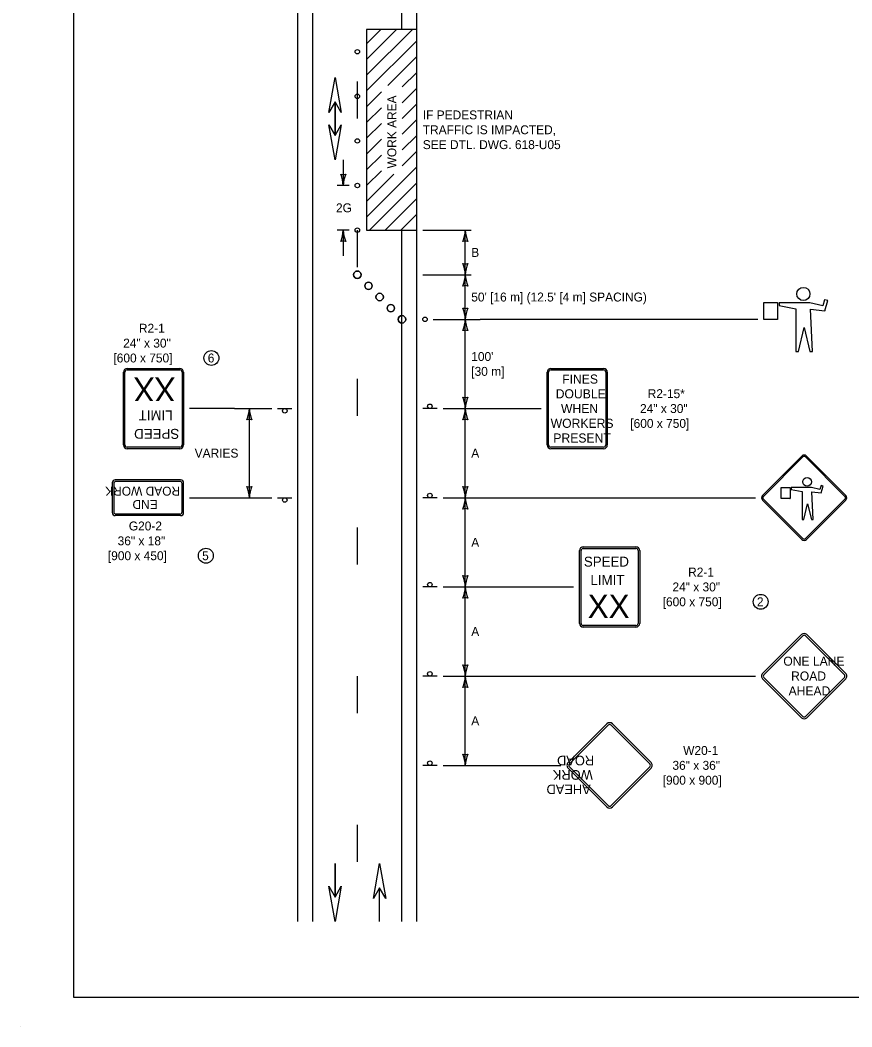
# Model space of a CAD drawing. Extents: x 49991.4 to 50021, y 49987.6 to 50011.4.
# Drawn here: x 49999.98 to 50005.57, y 49999.86 to 50006.63 of the extents above; entities that cross this region are included whole.
import ezdxf

# ---------------------------------------------------------------- set-up
doc = ezdxf.new("R2010")
doc.units = 0
for name, color, linetype in [('Level 1', 7, 'Continuous'), ('Level 2', 7, 'Continuous'), ('Level 3', 7, 'Continuous')]:
    doc.layers.add(name, color=color, linetype=linetype)

msp = doc.modelspace()

# ---------------------------------------------------------------- linework, layer by layer
at = {"layer": 'Level 1'}
for p, q in [((50001.8443, 50000.5714), (50001.8443, 50010.7538)), ((50001.9443, 50000.5714), (50001.9443, 50010.7538)), ((50002.5443, 50006.5714), (50002.5443, 50010.7538)), ((50002.6443, 50000.5714), (50002.6443, 50010.7538)), ((50002.3068, 50006.5714), (50002.3068, 50005.2214)), ((50002.3068, 50006.2634), (50002.6148, 50006.5714)), ((50002.3068, 50006.3694), (50002.5087, 50006.5714)), ((50002.3068, 50006.4755), (50002.4027, 50006.5714)), ((50002.6443, 50006.5714), (50002.3068, 50006.5714)), ((50002.3068, 50006.1573), (50002.6443, 50006.4948)), ((50002.4504, 50006.1948), (50002.6443, 50006.3887)), ((50002.5464, 50006.1847), (50002.6443, 50006.2827)), ((50002.2443, 50005.9716), (50002.2443, 50006.2216)), ((50002.3068, 50006.0512), (50002.4064, 50006.1508)), ((50002.5464, 50006.0787), (50002.6443, 50006.1766)), ((50002.094, 50006.0842), (50002.094, 50005.8583)), ((50002.0943, 50005.8584), (50002.0943, 50006.0843)), ((50002.0943, 50006.0842), (50002.0943, 50005.8583)), ((50002.0946, 50005.8584), (50002.0946, 50006.0843)), ((50002.5464, 50005.9726), (50002.6443, 50006.0705)), ((50002.3068, 50005.9452), (50002.4064, 50006.0447)), ((50002.3068, 50005.8391), (50002.4064, 50005.9387)), ((50002.5464, 50005.8665), (50002.6443, 50005.9645)), ((50002.5464, 50005.7605), (50002.6443, 50005.8584)), ((50002.3068, 50005.733), (50002.4064, 50005.8326)), ((50002.3068, 50005.627), (50002.4064, 50005.7265)), ((50002.5464, 50005.6544), (50002.6443, 50005.7523)), ((50002.3068, 50005.3088), (50002.6443, 50005.6463)), ((50002.3068, 50005.5209), (50002.4064, 50005.6205)), ((50002.3068, 50005.4148), (50002.4899, 50005.5979)), ((50002.3255, 50005.2214), (50002.6443, 50005.5402)), ((50002.4315, 50005.2214), (50002.6443, 50005.4341)), ((50002.5376, 50005.2214), (50002.6443, 50005.3281)), ((50002.2443, 50004.9716), (50002.2443, 50005.2216)), ((50002.3068, 50005.2214), (50002.6443, 50005.2214)), ((50002.5443, 50000.5714), (50002.5443, 50005.2214)), ((50002.6437, 50005.2214), (50002.6443, 50005.222)), ((50004.9783, 50004.6214), (50004.9783, 50004.7339)), ((50004.9783, 50004.7339), (50005.0702, 50004.7339)), ((50005.0702, 50004.7339), (50005.0702, 50004.6214)), ((50005.2874, 50004.7332), (50005.0805, 50004.7332)), ((50005.0805, 50004.7332), (50005.0805, 50004.7146)), ((50005.0805, 50004.7146), (50005.193, 50004.6924)), ((50005.3742, 50004.7132), (50005.2874, 50004.7332)), ((50005.3869, 50004.7528), (50005.3742, 50004.7132)), ((50005.4089, 50004.7473), (50005.3869, 50004.7528)), ((50005.3889, 50004.6785), (50005.4089, 50004.7473)), ((50001.9443, 50004.6448), (50001.9443, 50004.6811)), ((50005.193, 50004.6924), (50005.193, 50004.4061)), ((50005.3061, 50004.4061), (50005.2913, 50004.6895)), ((50005.2913, 50004.6895), (50005.3889, 50004.6785)), ((50005.0702, 50004.6214), (50004.9783, 50004.6214)), ((50005.2112, 50004.4061), (50005.2495, 50004.5674)), ((50005.2495, 50004.5674), (50005.2878, 50004.4061)), ((50005.193, 50004.4061), (50005.2112, 50004.4061)), ((50005.2878, 50004.4061), (50005.3061, 50004.4061)), ((50000.6709, 50003.7766), (50000.6709, 50004.2661)), ((50000.6815, 50003.7766), (50000.6815, 50004.2661)), ((50000.6963, 50004.2914), (50001.0507, 50004.2914)), ((50000.6963, 50004.2809), (50001.0507, 50004.2809)), ((50001.0655, 50004.2661), (50001.0655, 50003.7766)), ((50001.076, 50004.2661), (50001.076, 50003.7766)), ((50003.5203, 50003.7766), (50003.5203, 50004.2661)), ((50003.5308, 50003.7766), (50003.5308, 50004.2661)), ((50003.5456, 50004.2914), (50003.9, 50004.2914)), ((50003.5456, 50004.2809), (50003.9, 50004.2809)), ((50003.7228, 50004.2914), (50003.7228, 50004.2914)), ((50003.9148, 50004.2661), (50003.9148, 50003.7766)), ((50003.9254, 50004.2661), (50003.9254, 50003.7766)), ((50002.2443, 50003.9716), (50002.2443, 50004.2216)), ((50001.7083, 50004.0214), (50001.8043, 50004.0214)), ((50002.7803, 50004.0214), (50002.6843, 50004.0214)), ((50001.0507, 50003.7619), (50000.6963, 50003.7619)), ((50003.9, 50003.7619), (50003.5456, 50003.7619)), ((50001.0507, 50003.7513), (50000.6963, 50003.7513)), ((50000.8735, 50003.7513), (50000.8735, 50003.7513)), ((50003.9, 50003.7513), (50003.5456, 50003.7513)), ((50005.2336, 50003.702), (50004.9683, 50003.4368)), ((50005.2397, 50003.6959), (50004.9745, 50003.4306)), ((50005.5235, 50003.4306), (50005.2583, 50003.6959)), ((50005.5297, 50003.4368), (50005.2644, 50003.702)), ((50000.596, 50003.5214), (50000.596, 50003.3214)), ((50000.596, 50003.5214), (50000.596, 50003.3214)), ((50000.606, 50003.5164), (50000.606, 50003.3264)), ((50000.606, 50003.5164), (50000.606, 50003.3264)), ((50001.056, 50003.5414), (50000.616, 50003.5414)), ((50001.056, 50003.5414), (50000.616, 50003.5414)), ((50001.051, 50003.5314), (50000.621, 50003.5314)), ((50001.051, 50003.5314), (50000.621, 50003.5314)), ((50001.066, 50003.3264), (50001.066, 50003.5164)), ((50001.066, 50003.3264), (50001.066, 50003.5164)), ((50001.076, 50003.3214), (50001.076, 50003.5214)), ((50001.076, 50003.3214), (50001.076, 50003.5214)), ((50005.0934, 50003.4161), (50005.0934, 50003.4903)), ((50005.0934, 50003.4903), (50005.154, 50003.4903)), ((50005.154, 50003.4903), (50005.154, 50003.4161)), ((50005.2973, 50003.4899), (50005.1608, 50003.4899)), ((50005.1608, 50003.4899), (50005.1608, 50003.4776)), ((50005.3546, 50003.4767), (50005.2973, 50003.4899)), ((50005.3629, 50003.5029), (50005.3546, 50003.4767)), ((50005.3774, 50003.4992), (50005.3629, 50003.5029)), ((50005.3642, 50003.4538), (50005.3774, 50003.4992)), ((50001.7083, 50003.4214), (50001.8043, 50003.4214)), ((50002.7803, 50003.4214), (50002.6843, 50003.4214)), ((50005.1608, 50003.4776), (50005.235, 50003.463)), ((50005.235, 50003.463), (50005.235, 50003.2741)), ((50005.3095, 50003.2741), (50005.2998, 50003.4611)), ((50005.2998, 50003.4611), (50005.3642, 50003.4538)), ((50004.9683, 50003.4059), (50005.2336, 50003.1407)), ((50004.9745, 50003.4121), (50005.2397, 50003.1468)), ((50005.154, 50003.4161), (50005.0934, 50003.4161)), ((50005.247, 50003.2741), (50005.2722, 50003.3805)), ((50005.2583, 50003.1468), (50005.5235, 50003.4121)), ((50005.2644, 50003.1407), (50005.5297, 50003.4059)), ((50005.2722, 50003.3805), (50005.2975, 50003.2741)), ((50001.056, 50003.3014), (50000.616, 50003.3014)), ((50001.056, 50003.3014), (50000.616, 50003.3014)), ((50001.051, 50003.3114), (50000.621, 50003.3114)), ((50002.2443, 50002.9716), (50002.2443, 50003.2216)), ((50005.235, 50003.2741), (50005.247, 50003.2741)), ((50005.2975, 50003.2741), (50005.3095, 50003.2741)), ((50003.7635, 50003.0914), (50004.1179, 50003.0914)), ((50003.7635, 50003.0809), (50004.1179, 50003.0809)), ((50003.9407, 50003.0914), (50003.9407, 50003.0914)), ((50003.7382, 50002.5766), (50003.7382, 50003.0661)), ((50003.7487, 50002.5766), (50003.7487, 50003.0661)), ((50004.1327, 50003.0661), (50004.1327, 50002.5766)), ((50004.1432, 50003.0661), (50004.1432, 50002.5766)), ((50002.7803, 50002.8214), (50002.6843, 50002.8214)), ((50004.1179, 50002.5619), (50003.7635, 50002.5619)), ((50004.1179, 50002.5513), (50003.7635, 50002.5513)), ((50005.2303, 50002.5007), (50004.9696, 50002.24)), ((50005.2391, 50002.4919), (50004.9784, 50002.2312)), ((50005.2303, 50002.5007), (50005.2303, 50002.5007)), ((50005.2391, 50002.4919), (50005.2391, 50002.4919)), ((50005.5195, 50002.2312), (50005.2588, 50002.4919)), ((50005.5283, 50002.24), (50005.2676, 50002.5007)), ((50002.2443, 50001.9716), (50002.2443, 50002.2216)), ((50002.7803, 50002.2214), (50002.6843, 50002.2214)), ((50004.9696, 50002.2027), (50005.2303, 50001.942)), ((50004.9784, 50002.2115), (50005.2391, 50001.9508)), ((50005.2588, 50001.9508), (50005.5195, 50002.2115)), ((50005.2676, 50001.942), (50005.5283, 50002.2027)), ((50003.9221, 50001.9007), (50003.6613, 50001.64)), ((50003.9309, 50001.8919), (50003.6701, 50001.6312)), ((50003.9221, 50001.9007), (50003.9221, 50001.9007)), ((50003.9309, 50001.8919), (50003.9309, 50001.8919)), ((50004.2113, 50001.6312), (50003.9505, 50001.8919)), ((50004.22, 50001.64), (50003.9593, 50001.9007)), ((50002.7803, 50001.6214), (50002.6843, 50001.6214)), ((50003.6613, 50001.6027), (50003.9221, 50001.342)), ((50003.6701, 50001.6115), (50003.9309, 50001.3508)), ((50003.9505, 50001.3508), (50004.2113, 50001.6115)), ((50003.9593, 50001.342), (50004.22, 50001.6027)), ((50002.2443, 50000.9716), (50002.2443, 50001.2216)), ((50002.094, 50000.9615), (50002.094, 50000.7356)), ((50002.0943, 50000.9615), (50002.0943, 50000.7356)), ((50002.3937, 50000.5714), (50002.3937, 50000.7973)), ((50002.394, 50000.5714), (50002.394, 50000.7973)), ((49999.9766, 49999.8624), (49999.9766, 49999.8624))]:
    msp.add_line(p, q, dxfattribs=at)
for points in [[(50008.6146, 50011.2628), (50000.3356, 50011.2628), (50000.3356, 50000.0624), (50008.6146, 50000.0624)], [(50002.0526, 50006.012), (50002.0943, 50006.2485), (50002.1362, 50006.012), (50002.0943, 50006.0842)], [(50002.136, 50005.9306), (50002.0943, 50005.6941), (50002.0524, 50005.9306), (50002.0943, 50005.8584)], [(50002.352, 50000.725), (50002.3937, 50000.9615), (50002.4356, 50000.725), (50002.3937, 50000.7972)], [(50002.136, 50000.8079), (50002.0943, 50000.5714), (50002.0524, 50000.8079), (50002.0943, 50000.7357)]]:
    msp.add_lwpolyline(points, close=True, dxfattribs=at)
for points in [[(50005.3868, 50004.7526), (50005.387, 50004.7528)], [(50005.3883, 50004.6786), (50005.3892, 50004.6797)], [(50005.0698, 50004.6214), (50005.0702, 50004.6218)], [(50005.3629, 50003.5027), (50005.3629, 50003.5029)], [(50005.3638, 50003.4539), (50005.3644, 50003.4546)], [(50005.1537, 50003.4161), (50005.154, 50003.4164)]]:
    msp.add_lwpolyline(points, dxfattribs=at)
for centre, radius in [((50002.2443, 50006.4214), 0.015), ((50002.2443, 50006.1214), 0.015), ((50002.2443, 50005.8214), 0.015), ((50002.2443, 50005.5214), 0.015), ((50002.2443, 50005.2214), 0.015), ((50002.2443, 50004.9214), 0.025), ((50002.3193, 50004.8464), 0.025), ((50002.3943, 50004.7714), 0.025), ((50005.2438, 50004.7921), 0.0442), ((50002.4693, 50004.6964), 0.025), ((50002.5443, 50004.6214), 0.025), ((50002.6995, 50004.6214), 0.0152), ((50002.7323, 50004.0367), 0.0152), ((50001.7563, 50004.0061), 0.0152), ((50005.2685, 50003.5287), 0.0292), ((50001.7563, 50003.4061), 0.0152), ((50002.7323, 50003.4367), 0.0152), ((50002.7323, 50002.8367), 0.0152), ((50002.7323, 50002.2367), 0.0152), ((50002.7323, 50001.6366), 0.0152)]:
    msp.add_circle(centre, radius, dxfattribs=at)
for centre, radius, start, end in [((50002.2443, 50004.9214), 0.025, 0, 180), ((50002.2443, 50004.9214), 0.025, 180, 0), ((50002.3193, 50004.8464), 0.025, 0, 180), ((50002.3193, 50004.8464), 0.025, 180, 0), ((50002.3943, 50004.7714), 0.025, 0, 180), ((50002.3943, 50004.7714), 0.025, 180, 0), ((50002.4693, 50004.6964), 0.025, 0, 180), ((50002.4693, 50004.6964), 0.025, 180, 0), ((50002.5443, 50004.6214), 0.025, 0, 180), ((50002.5443, 50004.6214), 0.025, 180, 0), ((50000.6963, 50004.2661), 0.0253, 90, 180), ((50000.6963, 50004.2661), 0.0148, 90, 180), ((50001.0507, 50004.2661), 0.0253, 360, 90), ((50001.0507, 50004.2661), 0.0148, 360, 90), ((50003.5456, 50004.2661), 0.0253, 90, 180), ((50003.5456, 50004.2661), 0.0148, 90, 180), ((50003.9, 50004.2661), 0.0253, 0, 90), ((50003.9, 50004.2661), 0.0148, 0, 90), ((50000.6963, 50003.7766), 0.0253, 180, 270), ((50000.6963, 50003.7766), 0.0148, 180, 270), ((50001.0507, 50003.7766), 0.0148, 270, 360), ((50001.0507, 50003.7766), 0.0253, 270, 360), ((50003.5456, 50003.7766), 0.0253, 180, 270), ((50003.5456, 50003.7766), 0.0148, 180, 270), ((50003.9, 50003.7766), 0.0148, 270, 360), ((50003.9, 50003.7766), 0.0253, 270, 360), ((50005.249, 50003.6867), 0.0218, 45, 135), ((50005.249, 50003.6867), 0.0131, 45, 135), ((50000.6159, 50003.5214), 0.02, 90, 180), ((50000.6159, 50003.5214), 0.02, 90, 180), ((50000.621, 50003.5164), 0.015, 90, 180), ((50000.621, 50003.5164), 0.015, 90, 180), ((50001.051, 50003.5164), 0.015, 360, 90), ((50001.051, 50003.5164), 0.015, 360, 90), ((50001.0559, 50003.5214), 0.02, 0, 90), ((50004.9837, 50003.4214), 0.0218, 135, 225), ((50004.9837, 50003.4214), 0.0131, 135, 225), ((50005.5142, 50003.4214), 0.0131, 315, 45.00024), ((50005.5142, 50003.4214), 0.0218, 315, 45.00024), ((50000.616, 50003.3214), 0.02, 180, 270), ((50000.616, 50003.3214), 0.02, 180, 270), ((50000.621, 50003.3264), 0.015, 180, 270), ((50000.621, 50003.3264), 0.015, 180, 270), ((50001.051, 50003.3264), 0.015, 270, 0), ((50001.051, 50003.3264), 0.015, 270, 0), ((50001.056, 50003.3214), 0.02, 270, 0), ((50001.056, 50003.3214), 0.02, 270, 0), ((50003.7635, 50003.0661), 0.0253, 90, 180), ((50003.7635, 50003.0661), 0.0148, 90, 180), ((50004.1179, 50003.0661), 0.0253, 0, 90), ((50004.1179, 50003.0661), 0.0148, 0, 90), ((50005.249, 50003.1562), 0.0218, 225, 314.99957), ((50005.249, 50003.1562), 0.0131, 225, 314.99957), ((50003.7635, 50002.5766), 0.0253, 180, 270), ((50003.7635, 50002.5766), 0.0148, 180, 270), ((50004.1179, 50002.5766), 0.0148, 270, 360), ((50004.1179, 50002.5766), 0.0253, 270, 360), ((50005.249, 50002.4821), 0.0263, 45.00008, 134.99993), ((50005.249, 50002.4821), 0.0139, 45.00008, 134.99993), ((50004.9882, 50002.2214), 0.0263, 134.99993, 225.00008), ((50004.9882, 50002.2214), 0.0139, 134.99993, 225.00008), ((50005.5097, 50002.2214), 0.0139, 314.99993, 45.00007), ((50005.5097, 50002.2214), 0.0263, 314.99993, 45.00008), ((50005.249, 50001.9606), 0.0263, 225.00007, 314.99993), ((50005.249, 50001.9606), 0.0139, 225.00007, 314.99993), ((50003.9407, 50001.8821), 0.0263, 45.00008, 134.99993), ((50003.9407, 50001.8821), 0.0139, 45.00008, 134.99993), ((50003.68, 50001.6214), 0.0263, 134.99993, 225.00008), ((50003.68, 50001.6214), 0.0139, 134.99993, 225.00008), ((50004.2014, 50001.6214), 0.0139, 314.99993, 45.00007), ((50004.2014, 50001.6214), 0.0263, 314.99993, 45.00008), ((50003.9407, 50001.3606), 0.0263, 225.00007, 314.99993), ((50003.9407, 50001.3606), 0.0139, 225.00007, 314.99993)]:
    msp.add_arc(centre, radius, start, end, dxfattribs=at)
at = {"layer": 'Level 2'}
for centre in [(50001.2628, 50004.3614), (50001.2254, 50003.0314), (50004.9564, 50002.7214)]:
    msp.add_circle(centre, 0.0501, dxfattribs=at)
at = {"layer": 'Level 3'}
for p, q in [((50002.1493, 50005.6948), (50002.1493, 50005.5214)), ((50002.1893, 50005.5214), (50002.1093, 50005.5214)), ((50002.1893, 50005.2214), (50002.1093, 50005.2214)), ((50002.1493, 50005.2214), (50002.1493, 50005.0479)), ((50002.6843, 50005.2214), (50003.0103, 50005.2214)), ((50002.9703, 50004.9214), (50002.9703, 50005.2214)), ((50002.6843, 50004.9214), (50003.0103, 50004.9214)), ((50002.9703, 50004.6214), (50002.9703, 50004.9214)), ((50002.7548, 50004.6214), (50003.0703, 50004.6214)), ((50002.9703, 50004.0214), (50002.9703, 50004.6214)), ((50004.9383, 50004.6214), (50003.0703, 50004.6214)), ((50001.4183, 50004.0214), (50001.116, 50004.0214)), ((50001.4183, 50004.0214), (50001.6683, 50004.0214)), ((50001.5183, 50003.4214), (50001.5183, 50004.0214)), ((50002.8203, 50004.0214), (50003.4803, 50004.0214)), ((50002.9703, 50003.4214), (50002.9703, 50004.0214)), ((50001.116, 50003.4214), (50001.6683, 50003.4214)), ((50002.8203, 50003.4214), (50004.9219, 50003.4214)), ((50002.9703, 50002.8214), (50002.9703, 50003.4214)), ((50002.8203, 50002.8214), (50003.6982, 50002.8214)), ((50002.9703, 50002.2214), (50002.9703, 50002.8214)), ((50002.8203, 50002.2214), (50004.9219, 50002.2214)), ((50002.9703, 50001.6214), (50002.9703, 50002.2214)), ((50002.8203, 50001.6214), (50003.6136, 50001.6214))]:
    msp.add_line(p, q, dxfattribs=at)
for centre, radius, start, end in [((50001.9272, 50005.5122), 0.2223, 2.36048, 22.54399), ((50002.1493, 50005.6496), 0.0548, 252.13882, 287.86118), ((50002.382, 50005.5099), 0.233, 157.92284, 177.17269), ((50001.9166, 50005.2329), 0.233, 337.92284, 357.17269), ((50002.3714, 50005.2305), 0.2223, 182.36048, 202.54399), ((50002.7482, 50005.2305), 0.2223, 337.45601, 357.63952), ((50003.203, 50005.2329), 0.233, 182.82731, 202.07716), ((50002.1493, 50005.0932), 0.0548, 72.13882, 107.86118), ((50002.9703, 50005.0932), 0.0548, 72.13882, 107.86118), ((50002.9703, 50005.0496), 0.0548, 252.13882, 287.86118), ((50002.7376, 50004.9099), 0.233, 2.82731, 22.07716), ((50003.1924, 50004.9122), 0.2223, 157.45601, 177.63952), ((50002.7482, 50004.9305), 0.2223, 337.45601, 357.63952), ((50003.203, 50004.9329), 0.233, 182.82731, 202.07716), ((50002.9703, 50004.7932), 0.0548, 72.13882, 107.86118), ((50002.9703, 50004.7496), 0.0548, 252.13882, 287.86118), ((50002.7376, 50004.6099), 0.233, 2.82731, 22.07716), ((50003.1924, 50004.6122), 0.2223, 157.45601, 177.63952), ((50002.7482, 50004.6305), 0.2223, 337.45601, 357.63952), ((50003.203, 50004.6329), 0.233, 182.82731, 202.07716), ((50002.9703, 50004.4932), 0.0548, 72.13882, 107.86118), ((50002.9703, 50004.1496), 0.0548, 252.13882, 287.86118), ((50002.7376, 50004.0099), 0.233, 2.82731, 22.07716), ((50003.1924, 50004.0122), 0.2223, 157.45601, 177.63952), ((50001.2962, 50004.0305), 0.2223, 337.45601, 357.63952), ((50001.751, 50004.0329), 0.233, 182.82731, 202.07716), ((50002.7482, 50004.0305), 0.2223, 337.45601, 357.63952), ((50003.203, 50004.0329), 0.233, 182.82731, 202.07716), ((50001.5183, 50003.8932), 0.0548, 72.13882, 107.86118), ((50002.9703, 50003.8932), 0.0548, 72.13882, 107.86118), ((50001.5183, 50003.5496), 0.0548, 252.13882, 287.86118), ((50001.2856, 50003.4099), 0.233, 2.82731, 22.07716), ((50001.7404, 50003.4122), 0.2223, 157.45601, 177.63952), ((50002.9703, 50003.5496), 0.0548, 252.13882, 287.86118), ((50002.7376, 50003.4099), 0.233, 2.82731, 22.07716), ((50003.1924, 50003.4122), 0.2223, 157.45601, 177.63952), ((50002.7482, 50003.4305), 0.2223, 337.45601, 357.63952), ((50003.203, 50003.4329), 0.233, 182.82731, 202.07716), ((50002.9703, 50003.2932), 0.0548, 72.13882, 107.86118), ((50002.9703, 50002.9496), 0.0548, 252.13882, 287.86118), ((50002.7376, 50002.8099), 0.233, 2.82731, 22.07716), ((50003.1924, 50002.8122), 0.2223, 157.45601, 177.63952), ((50002.7482, 50002.8305), 0.2223, 337.45601, 357.63952), ((50003.203, 50002.8329), 0.233, 182.82731, 202.07716), ((50002.9703, 50002.6932), 0.0548, 72.13882, 107.86118), ((50002.9703, 50002.3496), 0.0548, 252.13882, 287.86118), ((50002.7376, 50002.2099), 0.233, 2.82731, 22.07716), ((50003.1924, 50002.2122), 0.2223, 157.45601, 177.63952), ((50002.7482, 50002.2305), 0.2223, 337.45601, 357.63952), ((50003.203, 50002.2329), 0.233, 182.82731, 202.07716), ((50002.9703, 50002.0932), 0.0548, 72.13882, 107.86118), ((50002.9703, 50001.7496), 0.0548, 252.13882, 287.86118), ((50002.7376, 50001.6099), 0.233, 2.82731, 22.07716), ((50003.1924, 50001.6122), 0.2223, 157.45601, 177.63952)]:
    msp.add_arc(centre, radius, start, end, dxfattribs=at)

# ---------------------------------------------------------------- texts
at = {"layer": 'Level 1'}
for s, height, p in [('FINES', 0.06118, (50003.6217, 50004.1891)), ('DOUBLE', 0.06118, (50003.5782, 50004.0899)), ('WHEN', 0.06118, (50003.6137, 50003.9908)), ('WORKERS', 0.06118, (50003.5443, 50003.8916)), ('PRESENT', 0.06118, (50003.5624, 50003.7925)), ('SPEED', 0.06695, (50003.7676, 50002.9582)), ('LIMIT', 0.06695, (50003.8119, 50002.8344)), ('XX', 0.15772, (50003.7936, 50002.6124)), ('ONE LANE', 0.06087, (50005.109, 50002.2915)), ('ROAD', 0.06087, (50005.161, 50002.1921)), ('AHEAD', 0.06087, (50005.1445, 50002.0917))]:
    msp.add_text(s, height=height, dxfattribs=at).set_placement(p)
for s, height, p in [('XX', 0.15772, (50001.0206, 50004.2303)), ('LIMIT', 0.06695, (50001.0022, 50004.0084)), ('SPEED', 0.06695, (50001.0466, 50003.8846)), ('ROAD WORK', 0.06, (50001.0523, 50003.4958)), ('ROAD WORK', 0.06, (50001.0523, 50003.4958)), ('END', 0.06, (50000.9018, 50003.4058)), ('END', 0.06, (50000.9018, 50003.4058)), ('ROAD', 0.06453, (50003.8365, 50001.6859)), ('WORK', 0.06453, (50003.8275, 50001.5891)), ('AHEAD', 0.06453, (50003.8137, 50001.4923))]:
    msp.add_text(s, height=height, rotation=180, dxfattribs=at).set_placement(p)
at = {"layer": 'Level 2'}
for s, rotation, p in [('WORK AREA', 90, (50002.5064, 50005.6368)), ('2G', 360, (50002.1006, 50005.3414))]:
    msp.add_text(s, height=0.06, rotation=rotation, dxfattribs=at).set_placement(p)
for s, p in [('IF PEDESTRIAN', (50002.6843, 50005.9664)), ('TRAFFIC IS IMPACTED,', (50002.6843, 50005.8664)), ('SEE DTL. DWG. 618-U05', (50002.6843, 50005.7664)), ('B', (50003.0103, 50005.0414)), ("50' [16 m] (12.5' [4 m] SPACING)", (50003.0103, 50004.7414)), ('R2-1', (50000.7752, 50004.5314)), ('24" x 30"', (50000.6696, 50004.4314)), ('[600 x 750]', (50000.604, 50004.3314)), ('6', (50001.2383, 50004.3314)), ("100'", (50003.0103, 50004.3414)), ('[30 m]', (50003.0103, 50004.2414)), ('R2-15*', (50004.1969, 50004.0914)), ('24" x 30"', (50004.1453, 50003.9914)), ('[600 x 750]', (50004.0798, 50003.8914)), ('VARIES', (50001.1503, 50003.6914)), ('A', (50003.0103, 50003.6914)), ('G20-2', (50000.7074, 50003.2014)), ('36" x 18"', (50000.6322, 50003.1014)), ('A', (50003.0103, 50003.0914)), ('[900 x 450]', (50000.5666, 50003.0014)), ('5', (50001.2005, 50003.0014)), ('R2-1', (50004.4688, 50002.8914)), ('24" x 30"', (50004.3632, 50002.7914)), ('[600 x 750]', (50004.2976, 50002.6914)), ('2', (50004.9313, 50002.6914)), ('A', (50003.0103, 50002.4914)), ('A', (50003.0103, 50001.8914)), ('W20-1', (50004.4355, 50001.6914)), ('36" x 36"', (50004.3632, 50001.5914)), ('[900 x 900]', (50004.2976, 50001.4914))]:
    msp.add_text(s, height=0.06, dxfattribs=at).set_placement(p)

doc.saveas('drawing.dxf')
